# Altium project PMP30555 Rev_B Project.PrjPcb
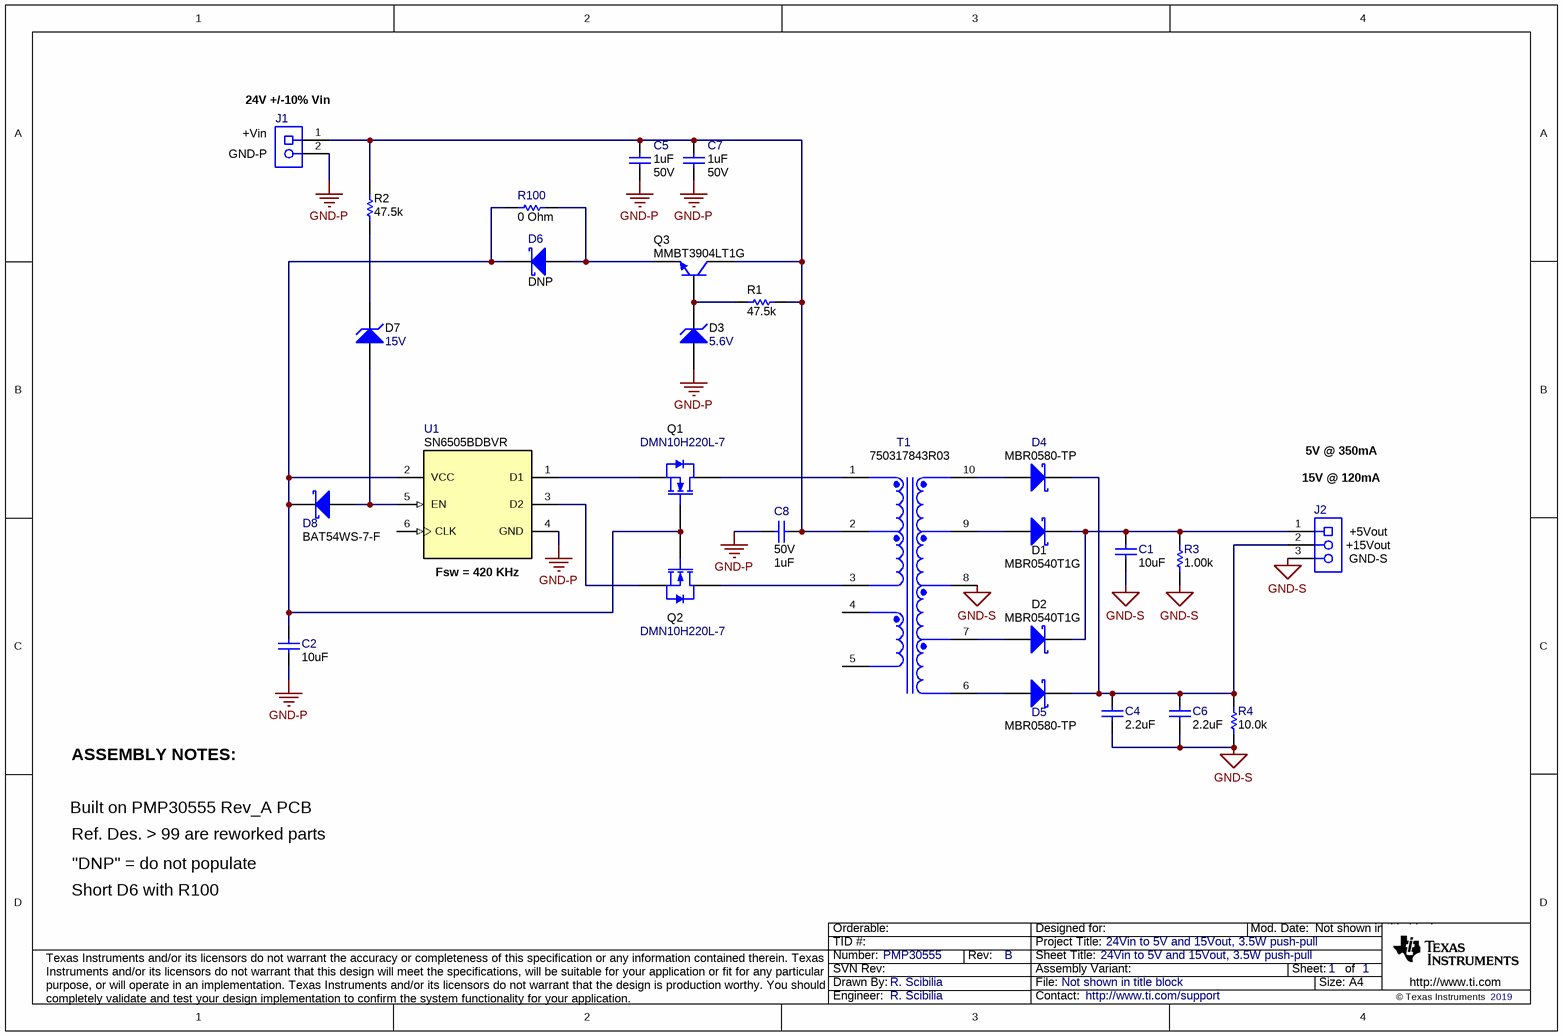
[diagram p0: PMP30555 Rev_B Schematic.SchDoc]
TechSupport: http://www.ti.com/support; SCH_Rev: B; PRJ_Title: 24Vin to 5V and 15Vout, 3.5W push-pull; PRJ_Number: PMP30555; PRJ_Engineer: R. Scibilia; PCB_Layout: R. Scibilia; CopyrightYear: 2019
1 sheet, 27 parts. Net scope: global (net labels, ports and power ports of the same name join across sheets).
Board file: PMP30555 Rev_A PCB.PcbDoc

## Sheet PMP30555 Rev_B Schematic.SchDoc: 24Vin to 5V and 15Vout, 3.5W push-pull
size A4; Date: Not shown in title block; ApprovedBy: Not shown in title block; CheckedBy: Not shown in title block; Author: Not shown in title block; CompanyName: Not shown in title block; DrawnBy: R. Scibilia; Engineer: Not shown in title block; Organization: Not shown in title block; Address1: Not shown in title block; Address2: Not shown in title block; Address3: Not shown in title block; Address4: Not shown in title block; DocumentNumber: 1; Revision: Use project parameter SCH_Rev; SheetNumber: 1; SheetTotal: 1; PageSetup: Record=PageOptions¦CenterHorizontal=True¦CenterVertical=True¦PrintScale=1.00¦XCorrection=1.00¦YCorrection=1.00¦PrintKind=0¦BorderSize=5000000¦LeftOffset=0¦BottomOffset=0¦Orientation=2¦PaperLength=1000¦PaperWidth=1000¦Scale=100¦PaperSource=15¦PrintQuality=600¦MediaType=1¦DitherType=10¦PaperKind=Letter¦PrintScaleMode=1

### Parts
C1  value 10uF  [0805_HV]  (hidden comment: 885012207026)
C2  value 10uF  [0805_HV]  (hidden comment: 885012207026)
C4  value 2.2uF  [0805_150]  (hidden comment: 08053C225KAT2A)
C5  VDC_V: 50V  ValueDisplayed: 1uF  [0805_HV]  (hidden comment: 08055C105KAT2A)
C6  value 2.2uF  [0805_150]  (hidden comment: 08053C225KAT2A)
C7  VDC_V: 50V  ValueDisplayed: 1uF  [0805_HV]  (hidden comment: 08055C105KAT2A)
C8  VDC_V: 50V  ValueDisplayed: 1uF  [0805_HV]  (hidden comment: 08055C105KAT2A)
D1  MBR0540T1G  [SOD-123]
D2  MBR0540T1G  [SOD-123]
D3  value 5.6V  [SOD-523]  (hidden comment: BZT52C5V6T-7)
D4  MBR0580-TP  [SOD-123]
D5  MBR0580-TP  [SOD-123]
D6  DNP  [SOD-323]
D7  value 15V  [SOD-323]  (hidden comment: BZX384-C15,115)
D8  BAT54WS-7-F  [SOD-323]
J1  39357-0002  [MOLEX_39357-0002]  (value not drawn)
J2  39357-0003  [MOLEX_39357-0003]  (value not drawn)
Q1  DMN10H220L-7  [SOT-23]
Q2  DMN10H220L-7  [SOT-23]
Q3  MMBT3904LT1G  [SOT-23]
R1  ValueDisplayed: 47.5k  [CMF50]  (hidden comment: CMF5047K500FHEB)
R2  ValueDisplayed: 47.5k  [CMF50]  (hidden comment: CMF5047K500FHEB)
R3  ValueDisplayed: 1.00k  [0603]  (hidden comment: ERJ-3EKF1001V)
R4  ValueDisplayed: 10.0k  [0603]  (hidden comment: RCG060310K0FKEA)
R100  ValueDisplayed: 0 Ohm  [0603]  (hidden comment: ERJ-3EKF1001V)
T1  750317843R03  [Wurth_750317843R00]
U1  SN6505BDBVR  [DBV0006A_L]

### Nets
GND-P: C2.2 C5.2 C7.2 C8.2 D3.2(A) J1.2 U1.4(GND)
GND-S: C1.2 C4.2 C6.2 J2.3 R3.1 R4.1 T1.8
NetC1_1: C1.1 D1.1(K) D2.1(K) J2.1 R3.2
NetC2_1: C2.1 D6.1(K) D8.1(K) Q1.1(G) Q2.1(G) R100.2 U1.2(VCC)
NetC4_1: C4.1 C6.1 D4.1(K) D5.1(K) J2.2 R4.2
NetC5_1: C5.1 C7.1 C8.1 J1.1 Q3.3(C) R1.1 R2.2 T1.2
NetD1_2: D1.2(A) T1.9
NetD2_2: D2.2(A) T1.7
NetD3_1: D3.1(K) Q3.1(B) R1.2
NetD4_2: D4.2(A) T1.10
NetD5_2: D5.2(A) T1.6
NetD6_2: D6.2(A) Q3.2(E) R100.1
NetD7_1: D7.1(K) R2.1
NetD7_2: D7.2(A) D8.2(A) U1.5(EN)
NetQ1_2: Q1.2(S) U1.1(D1)
NetQ1_3: Q1.3(D) T1.1
NetQ2_2: Q2.2(S) U1.3(D2)
NetQ2_3: Q2.3(D) T1.3

Not connected (* = marked no-connect by the designer): T1 4 5; U1 6(CLK)

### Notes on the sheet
- (near J1) 24V +/-10% Vin
- (near J1) GND-P
- (near J1) +Vin
- 5V @ 350mA
- (near J2) 15V @ 120mA
- (near U1) Fsw = 420 KHz
- (near J2) +5Vout
- (near J2) GND-S
- (near J2) +15Vout
- ASSEMBLY NOTES:
- Built on PMP30555 Rev_A PCB
- Ref. Des. > 99 are reworked parts
- Short D6 with R100
- "DNP" = do not populate

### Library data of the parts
C1 C2 = CMP-0007691-2: CAP, CERM, 10 uF, 10 V, +/- 10%, X7R, 0805; Manufacturer: Wurth Elektronik; TaMin_C: -55°C; Polarized: N; SizeAreaWB_mm2: 6.75; Value1: Unknown; U/M: EA; TaMax_C: 125°C; SizeZ_mm: 1.45; SizeX_mm: 2; SizeY_mm: 1.25; Cap_Case: 0805; Value2: 10V; SizeArea_mm2: 2.5; CompType: Capacitor; Cap_F: 10µF; AEC Category: Q200
C4 C6 = CMP-0007573-2: CAP, CERM, 2.2 uF, 25 V, +/- 10%, X7R, 0805; Manufacturer: AVX; TaMin_C: -55°C; Polarized: N; SizeAreaWB_mm2: 6.75; Value1: Unknown; U/M: EA; TaMax_C: 125°C; SizeZ_mm: 1.5; SizeX_mm: 2; SizeY_mm: 1.25; Cap_Case: 0805; Value2: 25V; SizeArea_mm2: 2.5; CompType: Capacitor; Cap_F: 2.2µF; AEC Category: Q200
C5 C7 C8 = CMP-0007634-2: CAP, CERM, 1 uF, 50 V, +/- 10%, X7R, 0805; Manufacturer: AVX; TaMin_C: -55°C; Polarized: N; SizeAreaWB_mm2: 6.75; Value1: Unknown; U/M: EA; Value: 1uF; TaMax_C: 125°C; SizeZ_mm: 1.45; SizeX_mm: 2; SizeY_mm: 1.25; Cap_Case: 0805; SizeArea_mm2: 2.5; Cap_F: 1µF; AEC Category: Q200
D1 D2 = MBR0540T1G: Diode, Schottky, 40 V, 0.5 A, SOD-123; Manufacturer: ON Semiconductor; U/M: EA; Vf_V: 0.51; Value1: 0.5A; Value2: 0.51V; Io_A: 0.5; Vr_V: 40; TJmax_C: 150; RJC_CperW: 118; SizeAreaWB_mm2: 13.095; SizeArea_mm2: 6.545; SizeX_mm: 3.85; SizeY_mm: 1.7; SizeZ_mm: 1.35; AEC Category: Q101; Green_Lifecycle: Active; Green_REACh: Passed
D3 = CMP-0005900-4: Diode, Zener, 5.6 V, 300 mW, SOD-523; Manufacturer: Diodes Inc.; AEC Category: Q101; SizeX_mm: 1.7; SizeArea_mm2: 1.53; RJA_CperW: 417; SizeY_mm: 0.9; Value1: 0.3W; SizeZ_mm: 0.65; Power_W: 300mW; SizeAreaWB_mm2: 5.13
D4 D5 = CMP-0077000-1: Diode, Schottky, 80 V, 0.5 A, SOD-123; Manufacturer: Micro Commercial Components; SizeAreaWB_mm2: 13.095; Vr_V: 80V; SizeArea_mm2: 6.545; TJmax_C: 150°C; AEC Category: Q101; SizeZ_mm: 1.35; Green_REACh: Incomplete; Io_A: 5dA; Vf_V: 8dV; SizeY_mm: 1.7; Value2: 0.8V; Green_Lifecycle: Not Set; U/M: EA; Value1: 0.5A; SizeX_mm: 3.85
D6 = CMP-0028458-1: Manufacturer: Diodes Inc.; Io_A: 2dA; Green_Lifecycle: Active; SizeAreaWB_mm2: 8.695; Vr_V: 30V; Green_REACh: Passed; Value1: 0.2A; TJmax_C: 125°C; U/M: EA; SizeZ_mm: 1; SizeX_mm: 2.7; SizeY_mm: 1.35; Vf_V: 7dV; Value2: 0.7V; SizeArea_mm2: 3.645; CompType: Diode; Type: Schottky; AEC Category: Q101
D7 = CMP-0005844-4: Diode, Zener, 15 V, 300 mW, SOD-323; Manufacturer: NXP Semiconductor; Value1: 0.3W; SizeY_mm: 1.35; SizeArea_mm2: 3.645; SizeX_mm: 2.7; SizeZ_mm: 1; SizeAreaWB_mm2: 8.695; AEC Category: Q101; Power_W: 300mW; RJA_CperW: 415
D8 = CMP-0028458-1: Diode, Schottky, 30 V, 0.2 A, SOD-323; Manufacturer: Diodes Inc.; Io_A: 2dA; Green_Lifecycle: Active; SizeAreaWB_mm2: 8.695; Vr_V: 30V; Green_REACh: Passed; Value1: 0.2A; TJmax_C: 125°C; U/M: EA; SizeZ_mm: 1; SizeX_mm: 2.7; SizeY_mm: 1.35; Vf_V: 7dV; Value2: 0.7V; SizeArea_mm2: 3.645; AEC Category: Q101
J1 = CMP-0055341-1: Terminal Block, 3.5 mm, 2x1, Tin, TH; Manufacturer: Molex; CNHeader: FALSE; Green_Lifecycle: Not Set; Green_REACh: Incomplete; CT: TRUE
J2 = CMP-0055340-1: Terminal Block, 3.5 mm, 3x1, Tin, TH; Manufacturer: Molex; CNHeader: FALSE; Green_Lifecycle: Not Set; Green_REACh: Incomplete; CT: TRUE
Q1 Q2 = CMP-0000971-2: MOSFET, N-CH, 100 V, 1.4 A, SOT-23; Alternate Manufacturer: None; Manufacturer: Diodes Inc.; SizeZ_mm: 1.1; ChType: N; Value2: 4.1 nC; Value1: 0.2; VdsMax_V: 100V; SizeX_mm: 2.5; SizeY_mm: 3; Vgs_V: 16V; Value: 100V; Rdson45_ohm: 0.25; SizeArea_mm2: 7.5; AEC Category: Q101; IdsMax_A: 1.4A; SizeAreaWB_mm2: 14; U/M: EA; QgTyp_nC: 4.1
Q3 = MMBT3904LT1G, ON Semiconductor: Transistor, NPN, 40 V, 0.2 A, SOT-23; CompType: BJT; PNP: 0; NPN: 1; Vceo_V: 40; Vcesat1_V: 0.3; IcRated_A: 0.2; Value1: 0.2 A; HfeMax: 300; TaMin_C: -55; TaMax_C: 150; SizeAreaWB_mm2: 14; SizeArea_mm2: 7.5; SizeX_mm: 2.5; SizeY_mm: 3; SizeZ_mm: 1.1; U/M: EA; AEC Category: Q101; Green_Lifecycle: Active; Green_REACh: Passed
R1 R2 = CMP-0014869-3: RES, 47.5 k, 1%, 0.25 W, Axial; Manufacturer: Vishay-Dale; Power_W: 250mW; TempCo: 50 ppm/C; Value_Code: 47k5; Value: 47.5k; EIA_Code: E96; Value2: 0.25W; AEC Qualified: N; VDC_V: 200V; AEC Category: Q200; SizeAreaWB_mm2: 45.625; SizeArea_mm2: 17.325; SizeX_mm: 10.5; SizeY_mm: 1.65; SizeZ_mm: 2.03
R3 = CMP-0022680-4: RES, 1.00 k, 1%, 0.1 W, 0603; Manufacturer: Panasonic; Power_W: 100mW; TempCo: 100 ppm/C; Value_Code: 1k00; U/M: EA; Value: 1.00k; EIA_Code: E96; Res_ohm: 1k; SizeX_mm: 1.6; SizeY_mm: 0.8; SizeZ_mm: 1; SizeArea_mm2: 1.28; VDC_V: 75V; AEC Category: Q200; Value2: 0.1W
R4 = CMP-0023337-3: RES, 10.0 k, 1%, 0.1 W, 0603; Manufacturer: Vishay Draloric; Power_W: 100mW; TempCo: 100 ppm/C; Value_Code: 10k0; U/M: EA; Value: 10.0k; EIA_Code: E96; Res_ohm: 10k; SizeX_mm: 1.6; SizeY_mm: 0.8; SizeZ_mm: 1; Value2: 0.1W; SizeArea_mm2: 1.28; AEC Qualified: N; VDC_V: 75V; AEC Category: Q200
R100 = CMP-0022680-4: RES, 1.00 k, 1%, 0.1 W, 0603; Manufacturer: Panasonic; Power_W: 100mW; TempCo: 100 ppm/C; U/M: EA; Value: 0 Ohm; EIA_Code: E96; SizeX_mm: 1.6; SizeY_mm: 0.8; SizeZ_mm: 1; SizeArea_mm2: 1.28; AEC Category: Q200; Value2: 0.1W
T1 = CMP-0083966-1: Transformer, 1470 uH, SMT; Manufacturer: Wurth Elektronik; SizeAreaWB_mm2: 198.998; SizeArea_mm2: 146.538; AEC Qualified: N; Ns2toNp: 0.22; Lp: 1.47mH; AEC Category: Q200; SizeZ_mm: 1.98; Ind_H: 3.43mH; SizeY_mm: 12.6; Ns1toNp: 0.658; Rsec2_ohm: 1.049; Rsec1_ohm: 2.844; DCR_ohm: 4.656; SizeX_mm: 11.63
U1 = CMP-0076095-1: Low-Noise 1 A, 420 kHz Transformer Driver, DBV0006A (SOT-23-6); Manufacturer: Texas Instruments; Alternate PartNumber: SN6505BDBVT; SizeAreaWB_mm2: 14.82; SizeArea_mm2: 8.12; SizeZ_mm: 1.45; Green_REACh: Passed; SizeY_mm: 2.9; Green_Lifecycle: Active; U/M: EA; CompType: IC; SizeX_mm: 2.8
